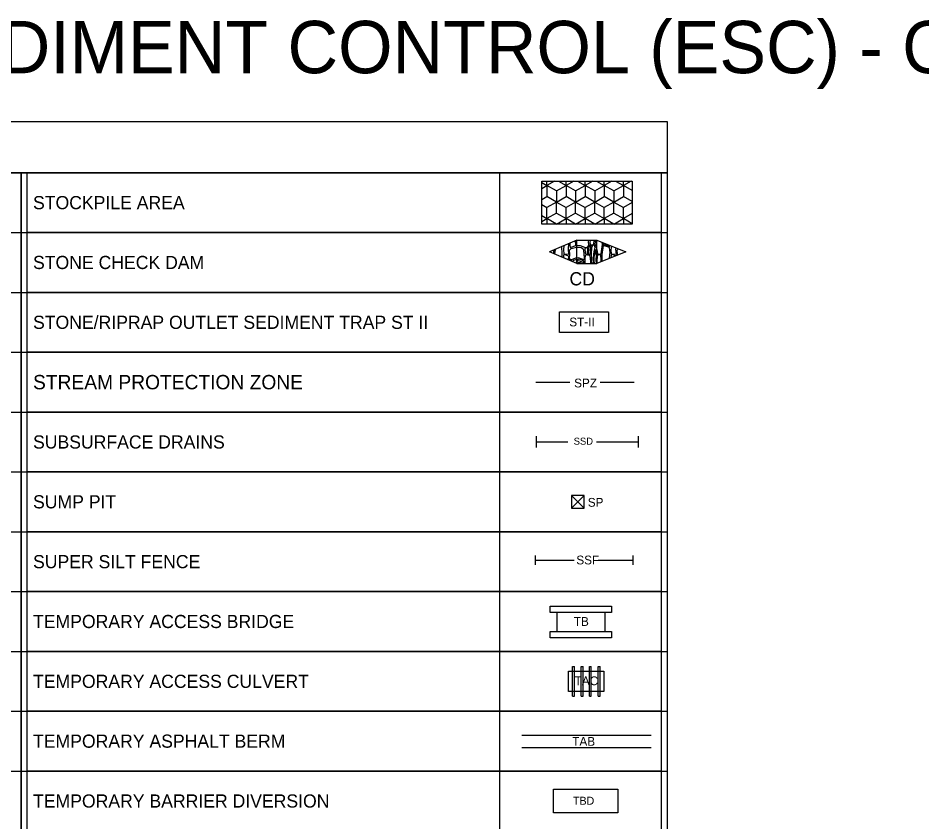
# Model space of a CAD drawing. Extents: x 1.3 to 34, y 0 to 22.5.
# Drawn here: x 12.78 to 20.33, y 14.4 to 21.12 of the extents above; entities that cross this region are included whole.
import ezdxf

# ---------------------------------------------------------------- set-up
doc = ezdxf.new("R2010")
doc.units = 0
for name, color, linetype in [('ANNO-NOTE', 7, 'Continuous'), ('ANNO-SYMB', 7, 'Continuous'), ('ANNO-TABL', 7, 'Continuous'), ('USER-LINE', 7, 'Continuous')]:
    doc.layers.add(name, color=color, linetype=linetype)

msp = doc.modelspace()

# ---------------------------------------------------------------- linework, layer by layer
at = {"layer": 'ANNO-SYMB'}
for p, q in [((17.15, 19.7434), (17.1938, 19.7181)), ((17.15, 19.6929), (17.1938, 19.7181)), ((17.1938, 19.7181), (17.1938, 19.7553)), ((17.2581, 19.7553), (17.1938, 19.7181)), ((17.1938, 19.7181), (17.1938, 19.626)), ((17.2736, 19.6721), (17.1938, 19.7181)), ((17.2736, 19.6721), (17.3534, 19.7181)), ((17.2891, 19.7553), (17.3534, 19.7181)), ((17.3534, 19.7181), (17.3534, 19.7553)), ((17.4177, 19.7553), (17.3534, 19.7181)), ((17.3534, 19.7181), (17.3534, 19.626)), ((17.4332, 19.6721), (17.3534, 19.7181)), ((17.4332, 19.6721), (17.513, 19.7181)), ((17.4488, 19.7553), (17.513, 19.7181)), ((17.513, 19.7181), (17.513, 19.7553)), ((17.5773, 19.7553), (17.513, 19.7181)), ((17.513, 19.7181), (17.513, 19.626)), ((17.5929, 19.6721), (17.513, 19.7181)), ((17.5929, 19.6721), (17.6727, 19.7181)), ((17.6084, 19.7553), (17.6727, 19.7181)), ((17.6727, 19.7181), (17.6727, 19.7553)), ((17.737, 19.7553), (17.6727, 19.7181)), ((17.6727, 19.7181), (17.6727, 19.626)), ((17.7525, 19.6721), (17.6727, 19.7181)), ((17.7525, 19.6721), (17.8323, 19.7181)), ((17.768, 19.7553), (17.8323, 19.7181)), ((17.8323, 19.7181), (17.8323, 19.7553)), ((17.8966, 19.7553), (17.8323, 19.7181)), ((17.8323, 19.7181), (17.8323, 19.626)), ((17.9068, 19.6751), (17.8323, 19.7181)), ((17.2736, 19.6721), (17.2736, 19.5799)), ((17.4332, 19.6721), (17.4332, 19.5799)), ((17.5929, 19.6721), (17.5929, 19.5799)), ((17.7525, 19.6721), (17.7525, 19.5799)), ((17.15, 19.6007), (17.1938, 19.626)), ((17.2736, 19.5799), (17.1938, 19.626)), ((17.2736, 19.5799), (17.1938, 19.5338)), ((17.2736, 19.5799), (17.3534, 19.626)), ((17.2736, 19.4877), (17.2736, 19.5799)), ((17.2736, 19.5799), (17.3534, 19.5338)), ((17.4332, 19.5799), (17.3534, 19.626)), ((17.4332, 19.5799), (17.3534, 19.5338)), ((17.4332, 19.5799), (17.513, 19.626)), ((17.4332, 19.4877), (17.4332, 19.5799)), ((17.4332, 19.5799), (17.513, 19.5338)), ((17.5929, 19.5799), (17.513, 19.626)), ((17.5929, 19.5799), (17.513, 19.5338)), ((17.5929, 19.5799), (17.6727, 19.626)), ((17.5929, 19.4877), (17.5929, 19.5799)), ((17.5929, 19.5799), (17.6727, 19.5338)), ((17.7525, 19.5799), (17.6727, 19.626)), ((17.7525, 19.5799), (17.6727, 19.5338)), ((17.7525, 19.5799), (17.8323, 19.626)), ((17.7525, 19.4877), (17.7525, 19.5799)), ((17.7525, 19.5799), (17.8323, 19.5338)), ((17.9068, 19.583), (17.8323, 19.626)), ((17.9068, 19.5768), (17.8323, 19.5338)), ((17.15, 19.5591), (17.1938, 19.5338)), ((17.1938, 19.4417), (17.1938, 19.5338)), ((17.2736, 19.4877), (17.1938, 19.4417)), ((17.2736, 19.4877), (17.3534, 19.4417)), ((17.3534, 19.4417), (17.3534, 19.5338)), ((17.4332, 19.4877), (17.3534, 19.4417)), ((17.4332, 19.4877), (17.513, 19.4417)), ((17.513, 19.4417), (17.513, 19.5338)), ((17.5929, 19.4877), (17.513, 19.4417)), ((17.5929, 19.4877), (17.6727, 19.4417)), ((17.6727, 19.4417), (17.6727, 19.5338)), ((17.7525, 19.4877), (17.6727, 19.4417)), ((17.7525, 19.4877), (17.8323, 19.4417)), ((17.8323, 19.4417), (17.8323, 19.5338)), ((17.9068, 19.4847), (17.8323, 19.4417)), ((17.15, 19.467), (17.1938, 19.4417)), ((17.15, 19.4164), (17.1938, 19.4417)), ((17.1938, 19.4417), (17.1938, 19.3947)), ((17.2736, 19.3956), (17.1938, 19.4417)), ((17.2736, 19.3956), (17.3534, 19.4417)), ((17.3534, 19.4417), (17.3534, 19.3947)), ((17.4332, 19.3956), (17.3534, 19.4417)), ((17.4332, 19.3956), (17.513, 19.4417)), ((17.513, 19.4417), (17.513, 19.3947)), ((17.5929, 19.3956), (17.513, 19.4417)), ((17.5929, 19.3956), (17.6727, 19.4417)), ((17.6727, 19.4417), (17.6727, 19.3947)), ((17.7525, 19.3956), (17.6727, 19.4417)), ((17.7525, 19.3956), (17.8323, 19.4417)), ((17.8323, 19.4417), (17.8323, 19.3947)), ((17.9068, 19.3987), (17.8323, 19.4417)), ((17.2736, 19.3956), (17.2736, 19.3947)), ((17.4332, 19.3956), (17.4332, 19.3947)), ((17.5929, 19.3956), (17.5929, 19.3947)), ((17.7525, 19.3956), (17.7525, 19.3947)), ((17.4433, 19.2624), (17.2163, 19.1644)), ((17.4433, 19.2624), (17.6107, 19.2624)), ((17.4433, 19.0674), (17.4433, 19.2624)), ((17.6107, 19.2624), (17.852, 19.1644)), ((17.6107, 19.0674), (17.6107, 19.2624)), ((17.4433, 19.0674), (17.2163, 19.1644)), ((17.852, 19.1644), (17.6107, 19.0674)), ((17.4433, 19.0674), (17.6107, 19.0674)), ((17.1, 18.075), (17.3855, 18.075)), ((17.6387, 18.075), (17.9229, 18.075)), ((17.1058, 17.575), (17.1058, 17.6222)), ((17.9589, 17.575), (17.9589, 17.6222)), ((17.1058, 17.5278), (17.1058, 17.575)), ((17.1058, 17.575), (17.369, 17.575)), ((17.6071, 17.575), (17.9589, 17.575)), ((17.9589, 17.5278), (17.9589, 17.575)), ((17.4, 17.0228), (17.5044, 17.1272)), ((17.4, 17.1272), (17.5044, 17.0228)), ((17.0988, 16.5874), (17.0988, 16.626)), ((17.9156, 16.5874), (17.9156, 16.626)), ((17.0988, 16.5488), (17.0988, 16.5874)), ((17.0994, 16.5874), (17.4217, 16.5874)), ((17.6229, 16.5874), (17.9162, 16.5874)), ((17.9156, 16.5488), (17.9156, 16.5874)), ((17.276, 16.1508), (17.276, 15.9914)), ((17.677, 16.1508), (17.677, 15.9915)), ((17.4086, 15.4521), (17.4086, 15.6979)), ((17.4086, 15.6979), (17.4233, 15.6979)), ((17.4233, 15.4521), (17.4233, 15.6979)), ((17.4806, 15.4521), (17.4806, 15.6979)), ((17.4806, 15.6979), (17.4953, 15.6979)), ((17.4953, 15.4521), (17.4953, 15.6979)), ((17.55, 15.4521), (17.55, 15.6979)), ((17.55, 15.6979), (17.5647, 15.6979)), ((17.5647, 15.4521), (17.5647, 15.6979)), ((17.6227, 15.4521), (17.6227, 15.6979)), ((17.6227, 15.6979), (17.6373, 15.6979)), ((17.6373, 15.4521), (17.6373, 15.6979)), ((17.4086, 15.4521), (17.4233, 15.4521)), ((17.4806, 15.4521), (17.4953, 15.4521)), ((17.55, 15.4521), (17.5647, 15.4521)), ((17.6227, 15.4521), (17.6373, 15.4521)), ((16.9844, 15.125), (18.0656, 15.125)), ((16.9844, 15.0225), (18.0656, 15.0225)), ((17.25, 14.4752), (17.25, 14.6748)), ((17.25, 14.6748), (17.7852, 14.6748)), ((17.7852, 14.6748), (17.7852, 14.4752)), ((17.7852, 14.4752), (17.25, 14.4752))]:
    msp.add_line(p, q, dxfattribs=at)
for points in [[(17.15, 19.7553), (17.9068, 19.7553), (17.9068, 19.3947), (17.15, 19.3947)], [(17.5314, 19.1424), (17.5347, 19.1941), (17.5259, 19.1974), (17.5105, 19.193), (17.5127, 19.1545), (17.5182, 19.1435)], [(17.5545, 19.1424), (17.56, 19.2062), (17.5512, 19.2217), (17.5413, 19.1908), (17.5391, 19.1457), (17.5435, 19.1424)], [(17.5017, 19.0718), (17.4697, 19.0862), (17.4532, 19.0873), (17.4554, 19.1027), (17.462, 19.1049), (17.5006, 19.0873)], [(17.3, 18.6613), (17.7083, 18.6613), (17.7083, 18.4887), (17.3, 18.4887)], [(17.4, 17.0228), (17.5044, 17.0228), (17.5044, 17.1272), (17.4, 17.1272)], [(17.2212, 16.2029), (17.7335, 16.2029), (17.7335, 16.15), (17.2212, 16.15)], [(17.2212, 15.9914), (17.7335, 15.9914), (17.7335, 15.9386), (17.2212, 15.9386)], [(17.375, 15.6612), (17.6688, 15.6612), (17.6688, 15.4888), (17.375, 15.4888)]]:
    msp.add_lwpolyline(points, close=True, dxfattribs=at)
for points in [[(17.5094, 19.2007), (17.4741, 19.2129), (17.4433, 19.214), (17.44, 19.2591), (17.4411, 19.2613)], [(17.5105, 19.2007), (17.5325, 19.204), (17.5413, 19.2129), (17.5446, 19.2261), (17.5424, 19.2437), (17.5446, 19.2624)], [(17.5556, 19.2624), (17.5512, 19.2393), (17.5589, 19.2261), (17.5667, 19.2206), (17.5865, 19.2283), (17.5898, 19.2624)], [(17.5997, 19.2624), (17.5931, 19.2294), (17.6019, 19.214), (17.6129, 19.1688), (17.6173, 19.1446)], [(17.2626, 19.1842), (17.2571, 19.1468)], [(17.321, 19.1401), (17.3221, 19.1567), (17.3177, 19.1996), (17.3067, 19.2029)], [(17.3364, 19.2162), (17.3309, 19.1809), (17.3342, 19.1479), (17.3761, 19.1435)], [(17.3761, 19.1435), (17.3728, 19.1853), (17.3761, 19.2327)], [(17.3849, 19.1401), (17.3827, 19.1776), (17.397, 19.1908), (17.4422, 19.204), (17.4807, 19.1996), (17.4939, 19.1919), (17.4984, 19.1765), (17.5017, 19.1401)], [(17.386, 19.2371), (17.3849, 19.2184), (17.3882, 19.1996)], [(17.3882, 19.1996), (17.4345, 19.2162), (17.4345, 19.2426), (17.4278, 19.2558)], [(17.5854, 19.1401), (17.5876, 19.1666), (17.5975, 19.2007), (17.592, 19.2184), (17.5733, 19.2173), (17.5667, 19.2018), (17.5633, 19.1401)], [(17.6173, 19.1446), (17.646, 19.1457), (17.657, 19.225), (17.6548, 19.2448)], [(17.7187, 19.1401), (17.7209, 19.1567), (17.7154, 19.1996), (17.6647, 19.2173), (17.6537, 19.1401)], [(17.6636, 19.2404), (17.6647, 19.2283), (17.7187, 19.2118)], [(17.7187, 19.2118), (17.7198, 19.2184)], [(17.733, 19.2129), (17.7286, 19.1809), (17.7319, 19.1479), (17.7749, 19.1435)], [(17.7749, 19.1435), (17.7704, 19.1853), (17.7715, 19.1974)], [(17.7826, 19.1401), (17.7804, 19.1776), (17.7925, 19.1886)], [(17.2494, 19.1501), (17.2538, 19.1809)], [(17.3199, 19.1203), (17.321, 19.139)], [(17.375, 19.0961), (17.3761, 19.1225), (17.375, 19.128), (17.3419, 19.1401), (17.332, 19.1346), (17.3309, 19.1159)], [(17.5017, 19.139), (17.5039, 19.1192), (17.5017, 19.0961), (17.4587, 19.1148), (17.4312, 19.1115), (17.3992, 19.0983), (17.3893, 19.0983), (17.3816, 19.1148), (17.3849, 19.139)], [(17.5578, 19.0674), (17.56, 19.0741), (17.5589, 19.1126), (17.5534, 19.1324), (17.5336, 19.1368), (17.5215, 19.1379), (17.5138, 19.1313), (17.5116, 19.1071), (17.5105, 19.0674)], [(17.5633, 19.139), (17.5655, 19.1115), (17.5667, 19.0774), (17.5744, 19.0707), (17.5843, 19.0685), (17.5821, 19.1082), (17.5854, 19.139)], [(17.5909, 19.0674), (17.5876, 19.0906), (17.5887, 19.1137), (17.5909, 19.139)], [(17.6063, 19.1401), (17.6041, 19.1666), (17.6019, 19.1776), (17.5975, 19.1798), (17.5931, 19.1655), (17.5909, 19.1401)], [(17.6063, 19.139), (17.603, 19.0939), (17.6041, 19.0674)], [(17.646, 19.0818), (17.646, 19.1005), (17.6449, 19.1346), (17.6316, 19.1379), (17.6184, 19.1368), (17.6129, 19.1236), (17.6096, 19.0873), (17.6107, 19.0674)], [(17.6537, 19.139), (17.6526, 19.1082), (17.6526, 19.084)], [(17.7176, 19.1104), (17.7187, 19.139)], [(17.7671, 19.1302), (17.7396, 19.1401), (17.7297, 19.1346), (17.7286, 19.1148)], [(17.7826, 19.1368), (17.7826, 19.139)], [(17.4003, 19.0862), (17.4014, 19.0884), (17.3948, 19.0884)], [(17.4102, 19.0818), (17.4179, 19.095), (17.4444, 19.1038), (17.4455, 19.0884), (17.4356, 19.0707)], [(17.4455, 19.0674), (17.4521, 19.0774), (17.4708, 19.0752), (17.484, 19.0674)]]:
    msp.add_lwpolyline(points, dxfattribs=at)
at = {"layer": 'ANNO-TABL'}
for p, q in [((2, 19.325), (18.2, 19.325)), ((2, 18.825), (18.2, 18.825)), ((2, 18.325), (18.2, 18.325)), ((2, 17.825), (18.2, 17.825)), ((2, 17.325), (18.2, 17.325)), ((2, 16.825), (18.2, 16.825)), ((2, 16.325), (18.2, 16.325)), ((2, 15.825), (18.2, 15.825)), ((2, 15.325), (18.2, 15.325)), ((2, 14.825), (18.2, 14.825))]:
    msp.add_line(p, q, dxfattribs=at)
for points in [[(2, 19.825), (18.2, 19.825), (18.2, 20.25), (2, 20.25)], [(7.4, 7.825), (12.8, 7.825), (12.8, 19.825), (7.4, 19.825)], [(12.8, 7.825), (18.2, 7.825), (18.2, 19.825), (12.8, 19.825)]]:
    msp.add_lwpolyline(points, close=True, dxfattribs=at)
at = {"layer": 'USER-LINE'}
for p, q in [((12.85, 19.325), (12.85, 19.825)), ((16.8, 19.825), (12.85, 19.825)), ((16.8, 19.325), (16.8, 19.825)), ((18.15, 19.825), (16.8, 19.825)), ((18.15, 19.325), (18.15, 19.825)), ((12.85, 18.825), (12.85, 19.325)), ((16.8, 19.325), (12.85, 19.325)), ((16.8, 18.825), (16.8, 19.325)), ((18.15, 19.325), (16.8, 19.325)), ((18.15, 18.825), (18.15, 19.325)), ((12.85, 18.325), (12.85, 18.825)), ((16.8, 18.825), (12.85, 18.825)), ((18.15, 18.825), (16.8, 18.825)), ((16.8, 18.325), (16.8, 18.825)), ((18.15, 18.325), (18.15, 18.825)), ((12.85, 17.825), (12.85, 18.325)), ((16.8, 18.325), (12.85, 18.325)), ((18.15, 18.325), (16.8, 18.325)), ((16.8, 17.825), (16.8, 18.325)), ((18.15, 17.825), (18.15, 18.325)), ((12.85, 17.325), (12.85, 17.825)), ((16.8, 17.825), (12.85, 17.825)), ((18.15, 17.825), (16.8, 17.825)), ((16.8, 17.325), (16.8, 17.825)), ((18.15, 17.325), (18.15, 17.825)), ((12.85, 16.825), (12.85, 17.325)), ((16.8, 17.325), (12.85, 17.325)), ((18.15, 17.325), (16.8, 17.325)), ((16.8, 16.825), (16.8, 17.325)), ((18.15, 16.825), (18.15, 17.325)), ((12.85, 16.325), (12.85, 16.825)), ((16.8, 16.825), (12.85, 16.825)), ((18.15, 16.825), (16.8, 16.825)), ((16.8, 16.325), (16.8, 16.825)), ((18.15, 16.325), (18.15, 16.825)), ((12.85, 15.825), (12.85, 16.325)), ((16.8, 16.325), (12.85, 16.325)), ((18.15, 16.325), (16.8, 16.325)), ((16.8, 15.825), (16.8, 16.325)), ((18.15, 15.825), (18.15, 16.325)), ((12.85, 15.325), (12.85, 15.825)), ((16.8, 15.825), (12.85, 15.825)), ((18.15, 15.825), (16.8, 15.825)), ((16.8, 15.325), (16.8, 15.825)), ((18.15, 15.325), (18.15, 15.825)), ((12.85, 14.825), (12.85, 15.325)), ((16.8, 15.325), (12.85, 15.325)), ((18.15, 15.325), (16.8, 15.325)), ((16.8, 14.825), (16.8, 15.325)), ((18.15, 14.825), (18.15, 15.325)), ((16.8, 14.825), (12.85, 14.825)), ((12.85, 14.325), (12.85, 14.825)), ((18.15, 14.825), (16.8, 14.825)), ((16.8, 14.325), (16.8, 14.825)), ((18.15, 14.325), (18.15, 14.825))]:
    msp.add_line(p, q, dxfattribs=at)

# ---------------------------------------------------------------- texts
at = {"layer": 'ANNO-NOTE'}
msp.add_text('EROSION AND SEDIMENT CONTROL (ESC) - GENERAL NOTES', height=0.4375, dxfattribs=at).set_placement((7.5826, 20.6562))
at = {"layer": 'ANNO-SYMB'}
for s, height, p in [(' CD', 0.11016, (17.3413, 18.8835)), ('ST-II', 0.07344, (17.3805, 18.5409)), ('SPZ', 0.07344, (17.4212, 18.0308)), ('SSD', 0.05875, (17.4173, 17.552)), ('SP', 0.07344, (17.5351, 17.0338)), ('SSF', 0.07344, (17.4394, 16.552)), ('TB', 0.07344, (17.4184, 16.0383)), ('TAC', 0.07344, (17.4254, 15.5423)), ('TAB', 0.07344, (17.4053, 15.0362)), ('TBD', 0.0661, (17.4124, 14.5441))]:
    msp.add_text(s, height=height, dxfattribs=at).set_placement(p)
at = {"layer": 'ANNO-TABL'}
for s, height, p in [('STOCKPILE AREA', 0.11, (12.9, 19.52)), ('STONE CHECK DAM', 0.11, (12.9, 19.02)), ('STONE/RIPRAP OUTLET SEDIMENT TRAP ST II', 0.11, (12.9, 18.52)), ('STREAM PROTECTION ZONE', 0.12, (12.9, 18.015)), ('SUBSURFACE DRAINS', 0.11, (12.9, 17.52)), ('SUMP PIT', 0.11, (12.9, 17.02)), ('SUPER SILT FENCE', 0.11, (12.9, 16.52)), ('TEMPORARY ACCESS BRIDGE', 0.11, (12.9, 16.02)), ('TEMPORARY ACCESS CULVERT', 0.11, (12.9, 15.52)), ('TEMPORARY ASPHALT BERM', 0.11, (12.9, 15.02)), ('TEMPORARY BARRIER DIVERSION', 0.11, (12.9, 14.52))]:
    msp.add_text(s, height=height, dxfattribs=at).set_placement(p)

doc.saveas('drawing.dxf')
